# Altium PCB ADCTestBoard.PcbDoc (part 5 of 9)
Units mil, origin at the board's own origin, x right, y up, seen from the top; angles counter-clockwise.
Board outline 11022.62 x 9187 mil, 8 copper layers (TopLayer, InternalPlane1, InternalPlane2, InternalPlane3, InternalPlane4, InternalPlane5, MidLayer1, BottomLayer), stack 103.8 mil thick; 1282 components, 637 nets, 4473 pads, 1306 vias.
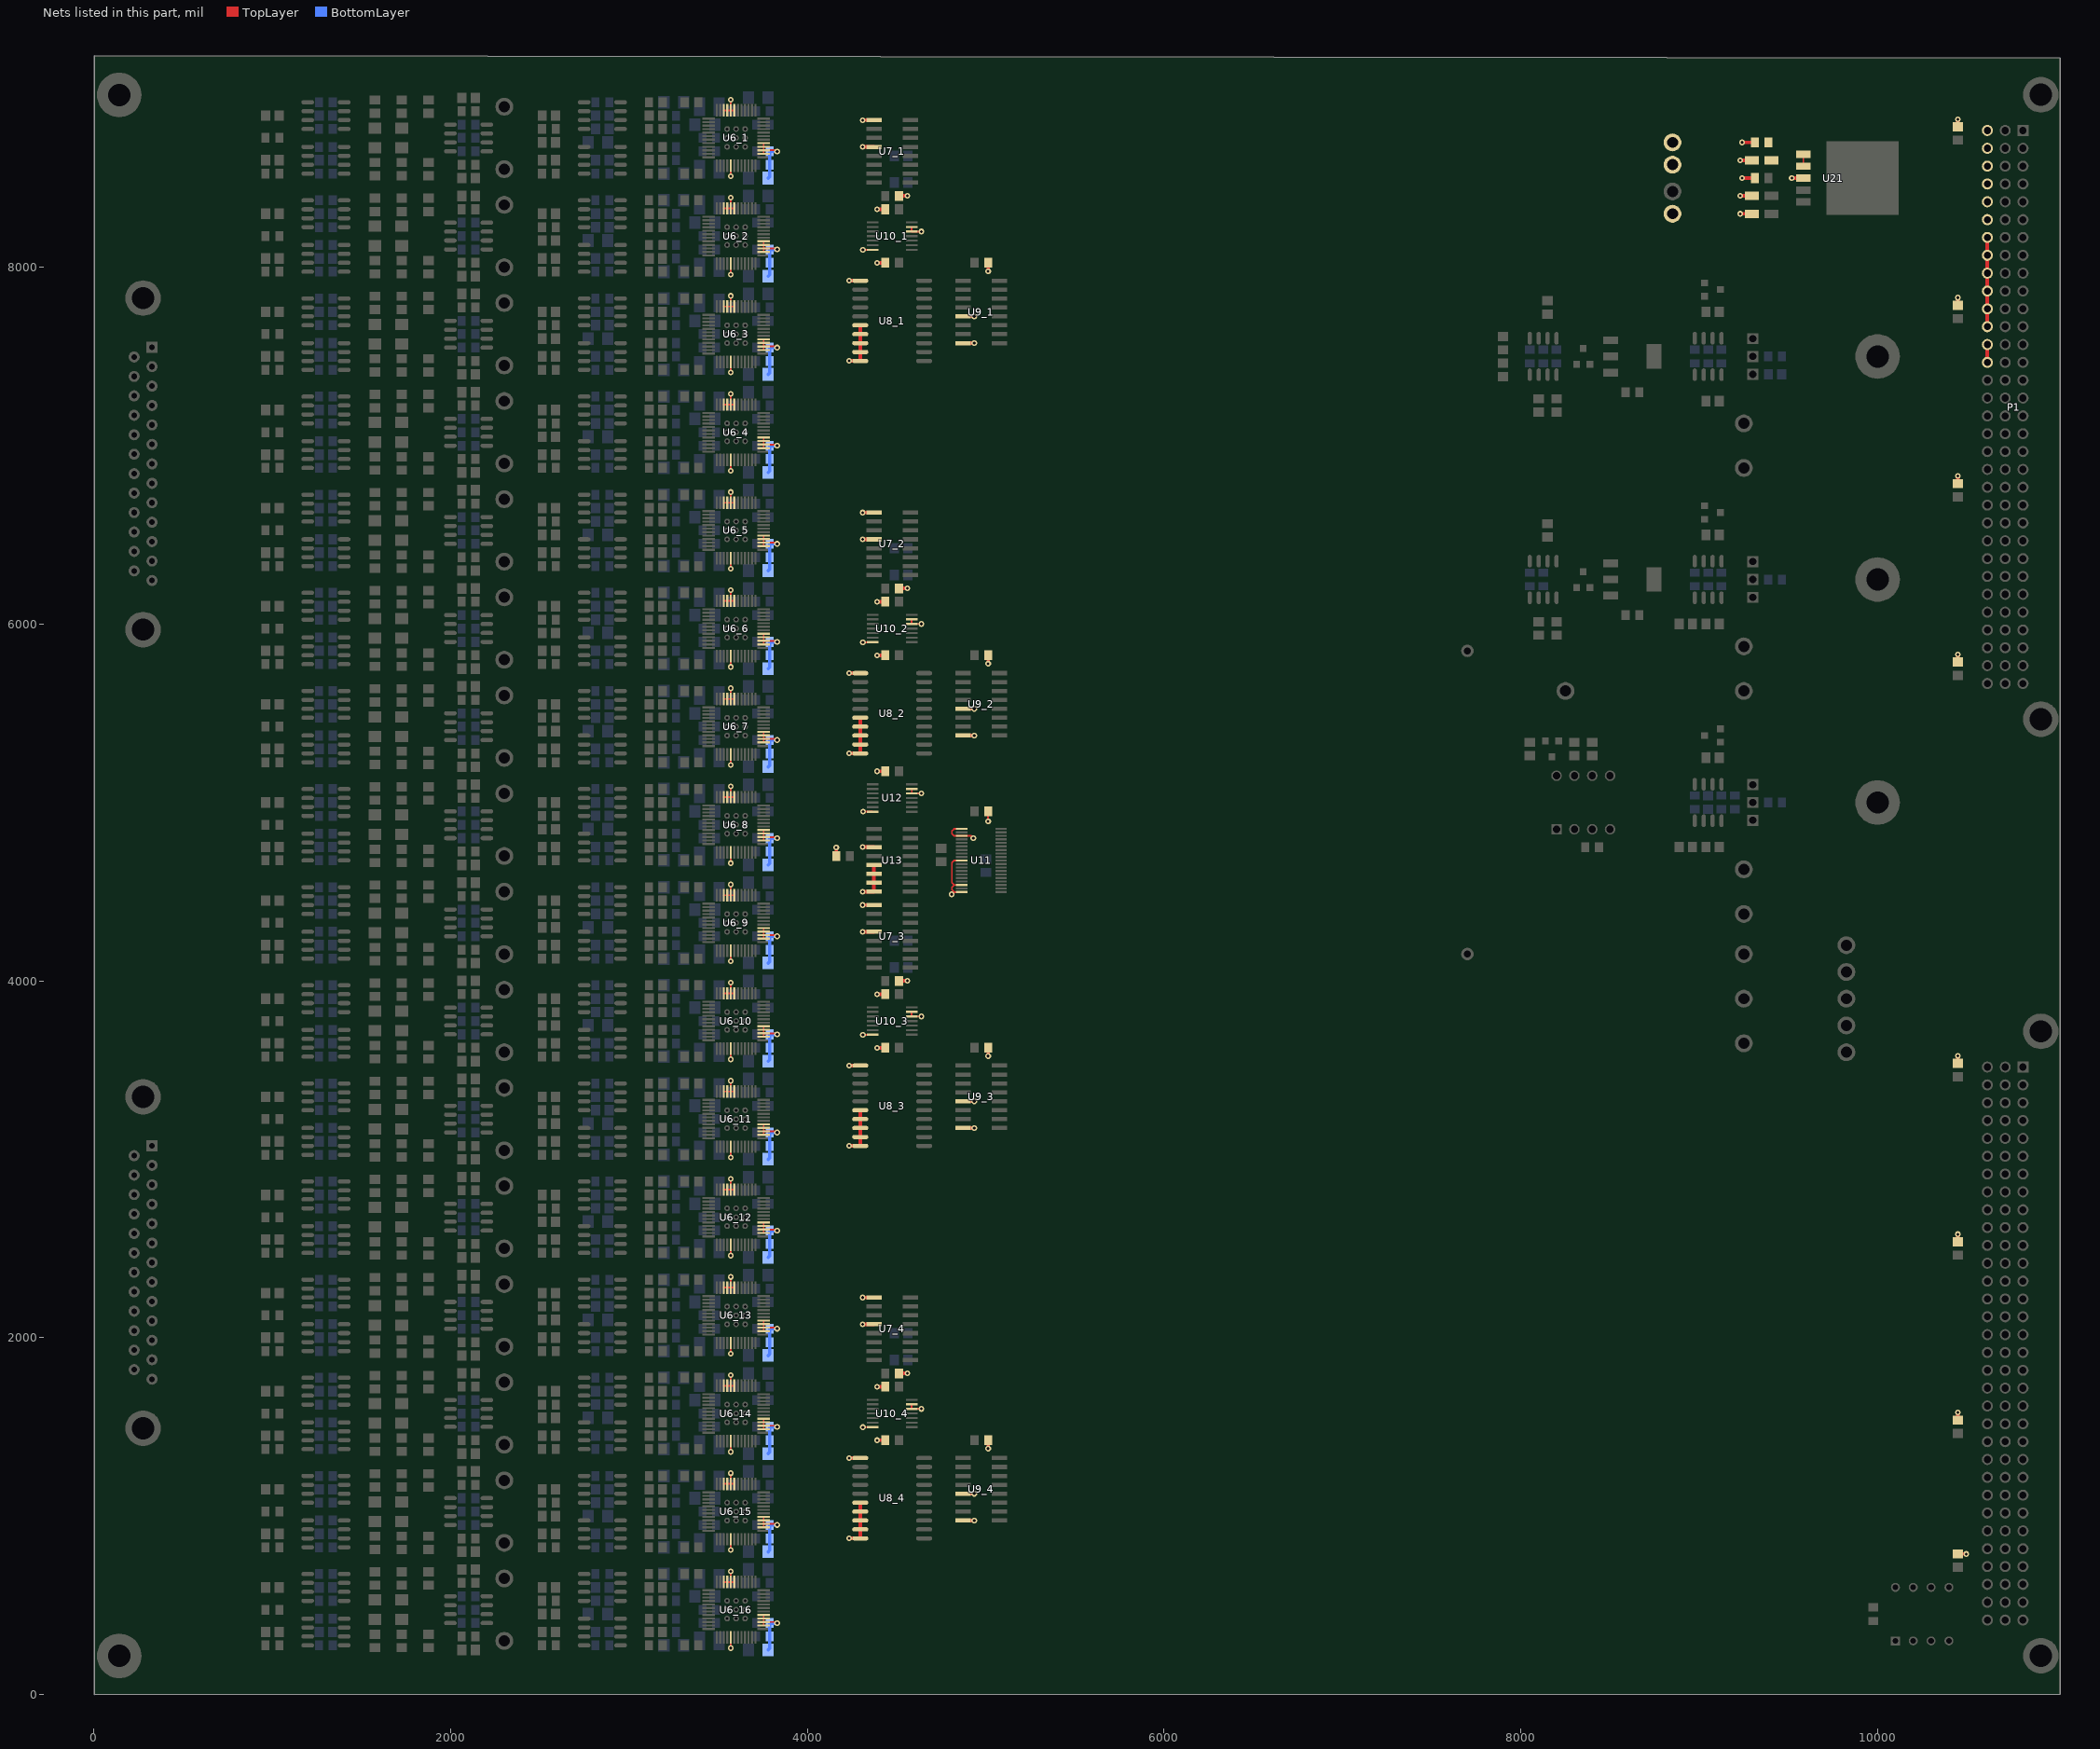
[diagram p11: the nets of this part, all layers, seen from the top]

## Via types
v1: diameter 32, hole 16, TopLayer to BottomLayer, 1306 vias

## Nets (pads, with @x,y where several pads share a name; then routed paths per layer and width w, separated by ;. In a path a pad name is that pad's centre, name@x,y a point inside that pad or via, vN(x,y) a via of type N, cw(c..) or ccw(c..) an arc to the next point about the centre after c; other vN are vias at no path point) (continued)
DGND: C23_1.1 C23_2.1 C23_3.1 C23_4.1 C23_5.1 C23_6.1 C23_7.1 C23_8.1 C23_9.1 C23_10.1 C23_11.1 C23_12.1 C23_13.1 C23_14.1 C23_15.1 C23_16.1 C24_1.1 C24_2.1 C24_3.1 C24_4.1 C24_5.1 C24_6.1 C24_7.1 C24_8.1 C24_9.1 C24_10.1 C24_11.1 C24_12.1 C24_13.1 C24_14.1 C24_15.1 C24_16.1 C25_1.1 C25_2.1 C25_3.1 C25_4.1 C25_5.1 C25_6.1 C25_7.1 C25_8.1 C25_9.1 C25_10.1 C25_11.1 C25_12.1 C25_13.1 C25_14.1 C25_15.1 C25_16.1 C43_1.2 C43_2.2 C43_3.2 C43_4.2 C44_1.2 C44_2.2 C44_3.2 C44_4.2 C45_1.2 C45_2.2 C45_3.2 C45_4.2 C46_1.2 C46_2.2 C46_3.2 C46_4.2 C75.2 C76.2 C77.2 C78.1 C79.1 C82.2 C83.2 C84.2 R45.2 R46.2 R47.2 R50.2 R51.2 R52.2 R53.2 R54.2 TP20.1 TP21.1 U6_1.5 U6_1.14 U6_1.15 U6_1.16 U6_1.17 U6_1.31 U6_1.32 U6_1.33 U6_1.34 U6_2.5 U6_2.14 U6_2.15 U6_2.16 U6_2.17 U6_2.31 U6_2.32 U6_2.33 U6_2.34 U6_3.5 U6_3.14 U6_3.15 U6_3.16 U6_3.17 U6_3.31 U6_3.32 U6_3.33 U6_3.34 U6_4.5 U6_4.14 U6_4.15 U6_4.16 U6_4.17 U6_4.31 U6_4.32 U6_4.33 U6_4.34 U6_5.5 U6_5.14 U6_5.15 U6_5.16 U6_5.17 U6_5.31 U6_5.32 U6_5.33 U6_5.34 U6_6.5 U6_6.14 U6_6.15 U6_6.16 U6_6.17 U6_6.31 U6_6.32 U6_6.33 U6_6.34 U6_7.5 U6_7.14 U6_7.15 U6_7.16 U6_7.17 U6_7.31 U6_7.32 U6_7.33 U6_7.34 U6_8.5 U6_8.14 U6_8.15 U6_8.16 U6_8.17 U6_8.31 U6_8.32 U6_8.33 U6_8.34 U6_9.5 U6_9.14 U6_9.15 U6_9.16 U6_9.17 U6_9.31 U6_9.32 U6_9.33 U6_9.34 U6_10.5 U6_10.14 U6_10.15 U6_10.16 U6_10.17 U6_10.31 U6_10.32 U6_10.33 U6_10.34 U6_11.5 U6_11.14 U6_11.15 U6_11.16 U6_11.17 U6_11.31 U6_11.32 U6_11.33 U6_11.34 U6_12.5 U6_12.14 U6_12.15 U6_12.16 U6_12.17 U6_12.31 U6_12.32 U6_12.33 U6_12.34 U6_13.5 U6_13.14 U6_13.15 U6_13.16 U6_13.17 U6_13.31 U6_13.32 U6_13.33 U6_13.34 U6_14.5 U6_14.14 U6_14.15 U6_14.16 U6_14.17 U6_14.31 U6_14.32 U6_14.33 U6_14.34 U6_15.5 U6_15.14 U6_15.15 U6_15.16 U6_15.17 U6_15.31 U6_15.32 U6_15.33 U6_15.34 U6_16.5 U6_16.14 U6_16.15 U6_16.16 U6_16.17 U6_16.31 U6_16.32 U6_16.33 U6_16.34 U7_1.9 U7_1.12 U7_2.9 U7_2.12 U7_3.9 U7_3.12 U7_4.9 U7_4.12 U8_1.1 U8_1.6 U8_1.7 U8_1.8 U8_1.9 U8_1.10 U8_2.1 U8_2.6 U8_2.7 U8_2.8 U8_2.9 U8_2.10 U8_3.1 U8_3.6 U8_3.7 U8_3.8 U8_3.9 U8_3.10 U8_4.1 U8_4.6 U8_4.7 U8_4.8 U8_4.9 U8_4.10 U9_1.5 U9_1.8 U9_2.5 U9_2.8 U9_3.5 U9_3.8 U9_4.5 U9_4.8 U10_1.7 U10_1.12 U10_1.13 U10_2.7 U10_2.12 U10_2.13 U10_3.7 U10_3.12 U10_3.13 U10_4.7 U10_4.12 U10_4.13 U11.1 U11.3 U11.10 U11.17 U11.19 U12.7 U12.12 U12.13 U13.3 U13.5 U13.6 U13.7 U13.8 U21.3 | length 13539.9
  TopLayer w8: U6_16.14@3755,386.42 U6_16.17@3755,445.47 ; U6_15.14@3755,936.42 U6_15.17@3755,995.47 ; U6_14.14@3755,1486.42 U6_14.17@3755,1545.47 ; U6_13.14@3755,2036.42 U6_13.17@3755,2095.47 ; U6_12.14@3755,2586.42 U6_12.17@3755,2645.47 ; U6_11.14@3755,3136.42 U6_11.17@3755,3195.47 ; U6_10.14@3755,3686.42 U6_10.17@3755,3745.47 ; U6_9.14@3755,4236.42 U6_9.17@3755,4295.47 ; U6_8.14@3755,4786.42 U6_8.17@3755,4845.47 ; U6_7.14@3755,5336.42 U6_7.17@3755,5395.47 ; U6_6.14@3755,5886.42 U6_6.17@3755,5945.47 ; U6_5.14@3755,6436.42 U6_5.17@3755,6495.47 ; U6_4.14@3755,6986.42 U6_4.17@3755,7045.47 ; U6_3.14@3755,7536.42 U6_3.17@3755,7595.47 ; U6_2.14@3755,8086.42 U6_2.17@3755,8145.47 ; U6_1.14@3755,8636.42 U6_1.17@3755,8695.47 ; U12.12@4584.25,5050.59 U12.13@4584.25,5076.18
  TopLayer w10: U6_16.34@3531.1,630 U6_16.31@3590.16,630 ; U6_15.34@3531.1,1180 U6_15.31@3590.16,1180 ; U6_14.34@3531.1,1730 U6_14.31@3590.16,1730 ; U6_13.34@3531.1,2280 U6_13.31@3590.16,2280 ; U6_12.34@3531.1,2830 U6_12.31@3590.16,2830 ; U6_11.34@3531.1,3380 U6_11.31@3590.16,3380 ; U6_10.34@3531.1,3930 U6_10.31@3590.16,3930 ; U6_9.34@3531.1,4480 U6_9.31@3590.16,4480 ; U6_8.34@3531.1,5030 U6_8.31@3590.16,5030 ; U6_7.34@3531.1,5580 U6_7.31@3590.16,5580 ; U6_6.34@3531.1,6130 U6_6.31@3590.16,6130 ; U6_5.34@3531.1,6680 U6_5.31@3590.16,6680 ; U6_4.34@3531.1,7230 U6_4.31@3590.16,7230 ; U6_3.34@3531.1,7780 U6_3.31@3590.16,7780 ; U6_2.34@3531.1,8330 U6_2.31@3590.16,8330 ; U6_1.34@3531.1,8880 U6_1.31@3590.16,8880 ; v1(3570,260) U6_16.5@3570.47,320 ; v1(3570,810) U6_15.5@3570.47,870 ; v1(3570,1360) U6_14.5@3570.47,1420 ; v1(3570,1910) U6_13.5@3570.47,1970 ; v1(3570,2460) U6_12.5@3570.47,2520 ; v1(3570,3010) U6_11.5@3570.47,3070 ; v1(3570,3560) U6_10.5@3570.47,3620 ; v1(3570,4110) U6_9.5@3570.47,4170 ; v1(3570,4660) U6_8.5@3570.47,4720 ; v1(3570,5210) U6_7.5@3570.47,5270 ; v1(3570,5760) U6_6.5@3570.47,5820 ; v1(3570,6310) U6_5.5@3570.47,6370 ; v1(3570,6860) U6_4.5@3570.47,6920 ; v1(3570,7410) U6_3.5@3570.47,7470 ; v1(3570,7960) U6_2.5@3570.47,8020 ; v1(3570,8510) U6_1.5@3570.47,8570 ; U6_16.32@3570.47,630 v1@3570.47,684.53 ; U6_15.32@3570.47,1180 v1@3570.47,1234.53 ; U6_14.32@3570.47,1730 v1@3570.47,1784.53 ; U6_13.32@3570.47,2280 v1@3570.47,2334.53 ; U6_12.32@3570.47,2830 v1@3570.47,2884.53 ; U6_11.32@3570.47,3380 v1@3570.47,3434.53 ; U6_10.32@3570.47,3930 v1@3570.47,3984.53 ; U6_9.32@3570.47,4480 v1@3570.47,4534.53 ; U6_8.32@3570.47,5030 v1@3570.47,5084.53 ; U6_7.32@3570.47,5580 v1@3570.47,5634.53 ; U6_6.32@3570.47,6130 v1@3570.47,6184.53 ; U6_5.32@3570.47,6680 v1@3570.47,6734.53 ; U6_4.32@3570.47,7230 v1@3570.47,7284.53 ; U6_3.32@3570.47,7780 v1@3570.47,7834.53 ; U6_2.32@3570.47,8330 v1@3570.47,8384.53 ; U6_1.32@3570.47,8880 v1@3570.47,8934.53 ; U6_16.15@3755,406.1 3823.9,406.1 v1(3830,400) ; U6_15.15@3755,956.1 3823.9,956.1 v1(3830,950) ; U6_14.15@3755,1506.1 3823.9,1506.1 v1(3830,1500) ; U6_13.15@3755,2056.1 3823.9,2056.1 v1(3830,2050) ; U6_12.15@3755,2606.1 3823.9,2606.1 v1(3830,2600) ; U6_11.15@3755,3156.1 3823.9,3156.1 v1(3830,3150) ; U6_10.15@3755,3706.1 3823.9,3706.1 v1(3830,3700) ; U6_9.15@3755,4256.1 3823.9,4256.1 v1(3830,4250) ; U6_8.15@3755,4806.1 3823.9,4806.1 v1(3830,4800) ; U6_7.15@3755,5356.1 3823.9,5356.1 v1(3830,5350) ; U6_6.15@3755,5906.1 3823.9,5906.1 v1(3830,5900) ; U6_5.15@3755,6456.1 3823.9,6456.1 v1(3830,6450) ; U6_4.15@3755,7006.1 3823.9,7006.1 v1(3830,7000) ; U6_3.15@3755,7556.1 3823.9,7556.1 v1(3830,7550) ; U6_2.15@3755,8106.1 3823.9,8106.1 v1(3830,8100) ; U6_1.15@3755,8656.1 3823.9,8656.1 v1(3830,8650) ; v1(4310.59,1498.23) U10_4.7@4365.75,1498.23 ; v1(4310.59,3698.23) U10_3.7@4365.75,3698.23 ; v1(4310.59,5898.23) U10_2.7@4365.75,5898.23 ; v1(4310.59,8098.23) U10_1.7@4365.75,8098.23 ; v1(4311.77,4948.23) U12.7@4365.75,4948.23 ; U10_4.13@4584.25,1626.18 U10_4.12@4584.25,1600.59 v1(4639.41,1600.59) ; U10_3.13@4584.25,3826.18 U10_3.12@4584.25,3800.59 v1(4639.41,3800.59) ; U12.12@4584.25,5050.59 v1(4638.23,5050.59) ; U10_2.13@4584.25,6026.18 U10_2.12@4584.25,6000.59 v1(4639.41,6000.59) ; U10_1.13@4584.25,8226.18 U10_1.12@4584.25,8200.59 v1(4639.41,8200.59) ; v1(4809.37,4485.04) 4822.17,4497.83 ; U11.19@4864.76,4497.83 4822.17,4497.83 ; U11.17@4864.76,4537.2 4822.17,4537.2 ; U11.10@4864.76,4675 4822.17,4675 4810,4662.83 4810,4549.37 4822.17,4537.2 ; U11.1@4864.76,4852.17 4822.17,4852.17 4810,4840 4810,4824.96 4822.17,4812.8 4917.2,4812.8 v1(4930,4800) ; v1(5013.39,4893.39) C82.2@5013.39,4950 ; 4822.17,4497.83 4810,4510 4810,4525.04 4822.17,4537.2
  TopLayer w20: C84.2@4161.61,4700 v1(4161.61,4748.39) ; v1(4233.23,875) U8_4.10@4295.87,875 U8_4.6@4295.87,1075 ; v1(4233.23,1325) U8_4.1@4295.87,1325 ; v1(4233.23,3075) U8_3.10@4295.87,3075 U8_3.6@4295.87,3275 ; v1(4233.23,3525) U8_3.1@4295.87,3525 ; v1(4233.23,5275) U8_2.10@4295.87,5275 U8_2.6@4295.87,5475 ; v1(4233.23,5725) U8_2.1@4295.87,5725 ; v1(4233.23,7475) U8_1.10@4295.87,7475 U8_1.6@4295.87,7675 ; v1(4233.23,7925) U8_1.1@4295.87,7925 ; v1(4310,2075) U7_4.12@4372.64,2075 ; v1(4310,2225) U7_4.9@4372.64,2225 ; v1(4310,4275) U7_3.12@4372.64,4275 ; v1(4310,4425) U7_3.9@4372.64,4425 ; v1(4310,4500) U13.8@4372.64,4500 U13.5@4372.64,4650 ; v1(4310,4750) U13.3@4372.64,4750 ; v1(4310,6475) U7_2.12@4372.64,6475 ; v1(4310,6625) U7_2.9@4372.64,6625 ; v1(4310,8675) U7_1.12@4372.64,8675 ; v1(4310,8825) U7_1.9@4372.64,8825 ; v1(4390,1425) C44_4.2@4436.61,1425 ; v1(4390,1725) C46_4.2@4436.61,1725 ; v1(4390,3625) C44_3.2@4436.61,3625 ; v1(4390,3925) C46_3.2@4436.61,3925 ; v1(4390,5175) C83.2@4436.61,5175 ; v1(4390,5825) C44_2.2@4436.61,5825 ; v1(4390,6125) C46_2.2@4436.61,6125 ; v1(4390,8025) C44_1.2@4436.61,8025 ; v1(4390,8325) C46_1.2@4436.61,8325 ; C43_4.2@4513.39,1800 v1(4560,1800) ; C43_3.2@4513.39,4000 v1(4560,4000) ; C43_2.2@4513.39,6200 v1(4560,6200) ; C43_1.2@4513.39,8400 v1(4560,8400) ; U9_4.8@4872.64,975 v1(4935.28,975) ; U9_4.5@4872.64,1125 v1(4935.28,1125) ; U9_3.8@4872.64,3175 v1(4935.28,3175) ; U9_3.5@4872.64,3325 v1(4935.28,3325) ; U9_2.8@4872.64,5375 v1(4935.28,5375) ; U9_2.5@4872.64,5525 v1(4935.28,5525) ; U9_1.8@4872.64,7575 v1(4935.28,7575) ; U9_1.5@4872.64,7725 v1(4935.28,7725) ; v1(5013.39,1378.39) C45_4.2@5013.39,1425 ; v1(5013.39,3578.39) C45_3.2@5013.39,3625 ; v1(5013.39,5778.39) C45_2.2@5013.39,5825 ; v1(5013.39,7978.39) C45_1.2@5013.39,8025 ; v1(9230,8300) C77.2@9294.88,8300 ; v1(9230,8400) C76.2@9294.88,8400 ; v1(9230,8600) C75.2@9294.88,8600 ; v1(9240,8500) C79.1@9311.61,8500 ; v1(9240,8700) C78.1@9311.61,8700 ; v1(9518.78,8500) U21.3@9583.66,8500 ; R54.2@10450,787.4 v1(10497.4,787.4) ; R53.2@10450,1537.4 v1(10450,1580) ; R52.2@10450,2537.4 v1(10450,2580) ; R51.2@10450,3537.4 v1(10450,3580) ; R50.2@10450,5787.4 v1(10450,5830) ; R47.2@10450,6787.4 v1(10450,6830) ; R46.2@10450,7787.4 v1(10450,7830) ; R45.2@10450,8787.4 v1(10450,8830)
  BottomLayer w10: v1@4310,1498.82 v1(4310.59,1498.23) ; v1@4310,3698.82 v1(4310.59,3698.23) ; v1@4310,5898.82 v1(4310.59,5898.23) ; v1@4310,8098.82 v1(4310.59,8098.23) ; v1(4639.41,1600.59) v1@4640,1600 ; v1(4639.41,3800.59) v1@4640,3800 ; v1(4639.41,6000.59) v1@4640,6000 ; v1(4639.41,8200.59) v1@4640,8200
  BottomLayer w20: C25_16.1@3780.12,250 3788.39,258.27 C24_16.1@3788.39,400 v1(3830,400) ; C25_15.1@3780.12,800 3788.39,808.27 C24_15.1@3788.39,950 v1(3830,950) ; C25_14.1@3780.12,1350 3788.39,1358.27 C24_14.1@3788.39,1500 v1(3830,1500) ; C25_13.1@3780.12,1900 3788.39,1908.27 C24_13.1@3788.39,2050 v1(3830,2050) ; C25_12.1@3780.12,2450 3788.39,2458.27 C24_12.1@3788.39,2600 v1(3830,2600) ; C25_11.1@3780.12,3000 3788.39,3008.27 C24_11.1@3788.39,3150 v1(3830,3150) ; C25_10.1@3780.12,3550 3788.39,3558.27 C24_10.1@3788.39,3700 v1(3830,3700) ; C25_9.1@3780.12,4100 3788.39,4108.27 C24_9.1@3788.39,4250 v1(3830,4250) ; C25_8.1@3780.12,4650 3788.39,4658.27 C24_8.1@3788.39,4800 v1(3830,4800) ; C25_7.1@3780.12,5200 3788.39,5208.27 C24_7.1@3788.39,5350 v1(3830,5350) ; C25_6.1@3780.12,5750 3788.39,5758.27 C24_6.1@3788.39,5900 v1(3830,5900) ; C25_5.1@3780.12,6300 3788.39,6308.27 C24_5.1@3788.39,6450 v1(3830,6450) ; C25_4.1@3780.12,6850 3788.39,6858.27 C24_4.1@3788.39,7000 v1(3830,7000) ; C25_3.1@3780.12,7400 3788.39,7408.27 C24_3.1@3788.39,7550 v1(3830,7550) ; C25_2.1@3780.12,7950 3788.39,7958.27 C24_2.1@3788.39,8100 v1(3830,8100) ; C25_1.1@3780.12,8500 3788.39,8508.27 C24_1.1@3788.39,8650 v1(3830,8650)
  other v1: 3570.47,690 3570.47,1240 3570.47,1790 3570.47,2340 3570.47,2890 3570.47,3440 3570.47,3990 3570.47,4540 3570.47,5090 3570.47,5640 3570.47,6190 3570.47,6740 3570.47,7290 3570.47,7840 3570.47,8390 3570.47,8940
DV1: C75.1 C78.2 P1.1C P1.2C P1.3C P1.4C P1.5C P1.6C TP6.1 U21.1 U21.2 | length 61.9
  TopLayer w10: U21.2@9583.66,8566.93 U21.1@9583.66,8628.86
DV2: P1.7C P1.8C P1.9C P1.10C P1.11C P1.12C | length 500
  TopLayer w20: P1.12C@10615.41,7667 P1.7C@10615.41,8167
DV3: P1.13C P1.14C | length 100
  TopLayer w20: P1.14C@10615.41,7467 P1.13C@10615.41,7567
